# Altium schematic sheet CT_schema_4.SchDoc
size 298 x 247 mm
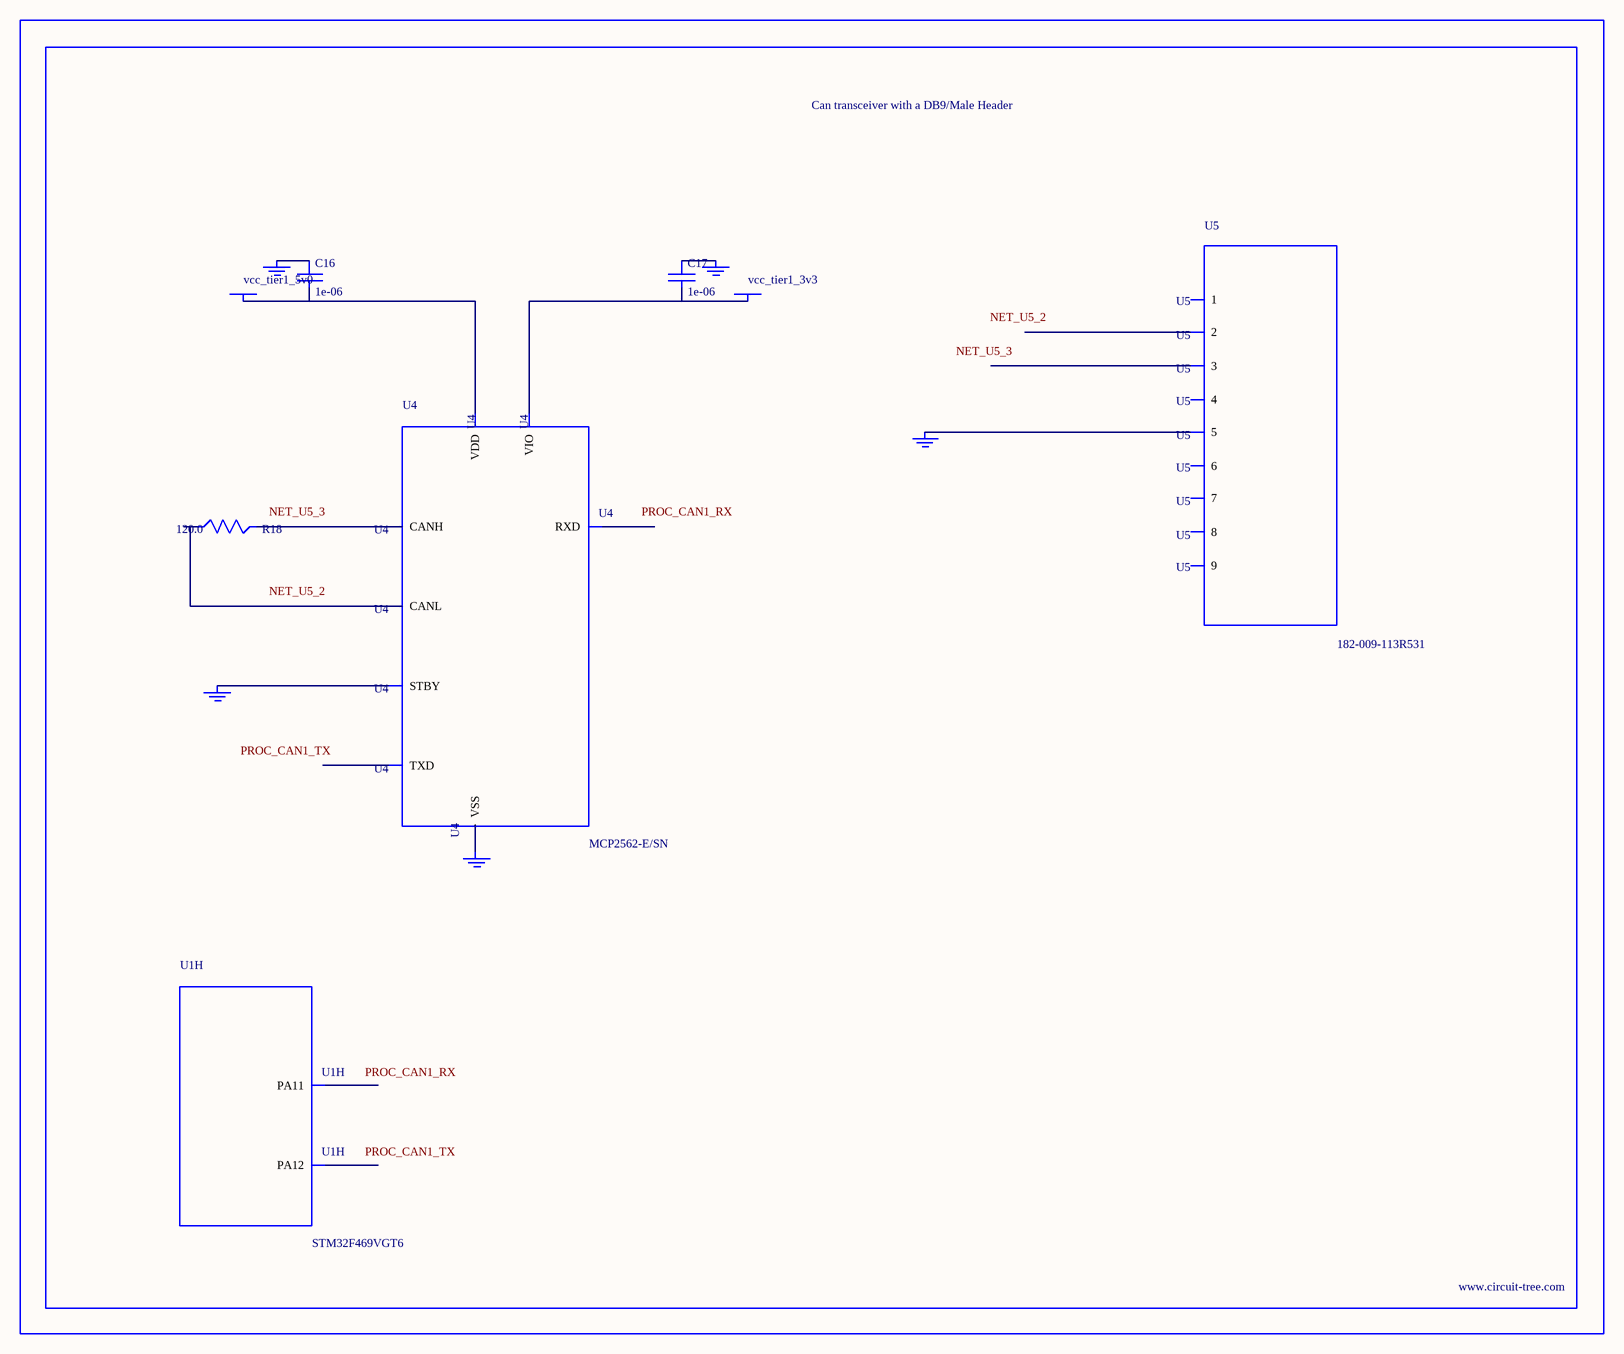
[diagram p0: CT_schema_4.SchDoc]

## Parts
BORDER3  (no value)
C16  1e-06  [C0603]
C17  1e-06  [C0603]
GND_INSTANCE_3_0  (no value)
GND_INSTANCE_3_1  (no value)
GND_INSTANCE_3_2  (no value)
GND_INSTANCE_3_3  (no value)
GND_INSTANCE_3_4  (no value)
POWER_INSTANCE_3_0  vcc_tier1_5v0
POWER_INSTANCE_3_1  vcc_tier1_3v3
R18  120.0  [R0603]
U1  STM32F469VGT6  [LQFP100]  (part H of 10)
U4  MCP2562-E/SN  [SOIC-8]
U5  182-009-113R531  [182-009-MALE]

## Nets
NetC16_1: C16.1 GND_INSTANCE_3_0.0(GND)
NetC16_2: C16.2 POWER_INSTANCE_3_0.0(PWR) U4.3(VDD)
NetC17_1: C17.1 GND_INSTANCE_3_1.0(GND)
NetC17_2: C17.2 POWER_INSTANCE_3_1.0(PWR) U4.5(VIO)
NetGND_INSTANCE_3_2_0: GND_INSTANCE_3_2.0(GND) U4.8(STBY)
NetGND_INSTANCE_3_3_0: GND_INSTANCE_3_3.0(GND) U4.2(VSS)
NetGND_INSTANCE_3_4_0: GND_INSTANCE_3_4.0(GND) U5.5
NetR18_1: R18.1 U4.6(CANL)
NetR18_2: R18.2 U4.7(CANH)

Not connected (* = marked no-connect by the designer): U1 73(PA11) 74(PA12); U4 1(TXD) 4(RXD); U5 1 2 3 4 6 7 8 9

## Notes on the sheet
- Labels drawn without touching a wire or pin: NET_U5_2, NET_U5_3, PROC_CAN1_RX, PROC_CAN1_TX

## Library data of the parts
BORDER3 = BORDER_PAGE3
C16 C17 = C0603C105K3RACTU
GND_INSTANCE_3_0-GND_INSTANCE_3_4 = GND
POWER_INSTANCE_3_0 POWER_INSTANCE_3_1 = PWR
R18 = RC0603JR-07120RL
